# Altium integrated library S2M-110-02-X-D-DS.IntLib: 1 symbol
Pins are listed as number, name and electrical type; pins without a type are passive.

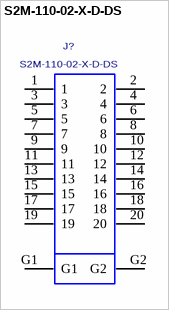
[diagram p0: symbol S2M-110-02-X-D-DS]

## S2M-110-02-X-D-DS
designator J?
2mm DOUBLE ROW SOCKET STRIP, 50 Pins, Dual Screw Down.; MANUFACTURER: SAMTEC
footprint S2M-110-02-X-D-DS
pins: 1, 2, 3, 4, 5, 6, 7, 8, 9, 10, 11, 12, 13, 14, 15, 16, 17, 18, 19, 20, G1, G2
